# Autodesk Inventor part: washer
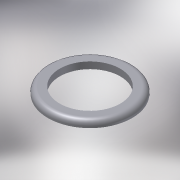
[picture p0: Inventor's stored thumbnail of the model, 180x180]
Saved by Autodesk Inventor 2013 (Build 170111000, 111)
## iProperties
Shininess: 25.0
Length Units: 11269
Angle Units: 11279
Time Units: 11290
Mass Units: 11283
Length Display Precision: 3
Angle Display Precision: 2
Created: 2002-03
Part Number: washer
Material: Steel, Mild
Document SubType Name: Modeling
Designer: =<Author>
Density: 7.86 g/cm^3
Description: =<Part Number>
Density: 7.86
Volumn: 1.0892290123242891
Area: 12.757152612383184
PropertySet Name: Model Information
Control State: 0
Master: False
Checked Out: True
Last Check In Date: 2008-10-15
Checked Out Date: 2008-10-15
Author: LAlexey
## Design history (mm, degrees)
sketch "Sketch1"
  geometry: C1 r 17 at (-11.557, 11.314); C2 r 12.25 at (-11.557, 11.314)
  constraints: 2 centre point, 1 coincident
  dimensions: "d0" = 34 diameter of C1; "d1" = 24.5 diameter of C2
extrude "Extrusion1" new body sketch "Sketch1" distance "d2" = 2.7; taper "d3" = 0 deg
fillet "Fillet1" dims "d4" = 2
body "Solid1"
